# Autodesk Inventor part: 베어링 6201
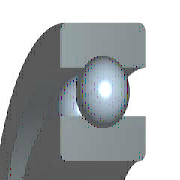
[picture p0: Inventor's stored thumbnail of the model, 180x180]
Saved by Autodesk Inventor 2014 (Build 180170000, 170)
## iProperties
Created: 2015-12
Part Number: 베어링 6201
Material: 강철, 연강
Description: 깊은 그루브 볼 베어링
Document SubType Name: Modeling
Standard: KS B 2023
Designer: mdu
Standards Organization: KS
Language: ko-KR
Size Designation: 6201 - 12 x 32 x 10
Categories: <MemberInstance><Categories><Category DisplayName="샤프트 부품" InternalName="7f7aeb1f-a693-4053-b835-cee3144e0d98" Mnemonic="SHFT"><Category DisplayName="베어링" Inter
Density: 7.86 g/cm^3
Mass: 32.7519 g
Surface Area: 42.5728 cm^2
Volume: 4.16691 cm^3
Appearance: 강철
Company: 한국ATC센터
IsCustomPart: 1
Author: mdu
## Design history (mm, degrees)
sketch "스케치" dims "d0" = 5.2 (= -0.26 x WD + 0.26 x BD)
  geometry: L1 (2.4, 11)-(7.6, 11); L2 (5, 11)-(5, 8.4); L3 (5, 11)-(5, 13.6); L4 (3.068, 9.26)-(0, 9.26); L5 (0, 6)-(10, 6); L6 (3.068, 12.74)-(0, 12.74); L7 (0, 16)-(10, 16); L8 (10, 6)-(10, 9.26); L9 (6.932, 9.26)-(10, 9.26); L10 (6.932, 12.74)-(10, 12.74); L11 (10, 16)-(10, 12.74); L12 (-1.4, 0)-(8.4, 0) reference; L13 (0, -0.3)-(0, 5.3) reference
  constraints: 22 end point, 4 point on line, 2 collinear, 2 perpendicular, 2 symmetric about line, 1 midpoint, 1 parallel, 14 other
  dimensions: "d9" = 12 diameter of L5 L12 (= WD); "d11" = 32 diameter of L7 L12 (= BD); "d12" = 10 distance between parallel lines of L8 L13 (= KB); "d13" = 18.52 diameter of L9 L12 (= 0.326 x BD + 0.674 x WD)
revolve "본체" stored, may be unused: angle "d6" = 90 deg
revolve "볼" stored, may be unused: angle "d7" = 90 deg
pattern_circular "IDS_ARRAYBALL[SIMPL:T]" dims angle "d3" = 360 deg
body "Solid1"
fillet "모깎기1" dims "d1" = 0.6 (= KRS)
other parameters: "WD" = 12 [user parameter; used in 5 equation terms], "BD" = 32 [user parameter; used in 5 equation terms], "KB" = 10 [user parameter; used in 1 equation term], "KRS" = 0.6 [user parameter; used in 1 equation term], "d4" = 0, "d5" = 0, "d8" = 0, "d14" = 0, "d15" = 0, "BBA" = 0 [user parameter], "BC0" = 3100000 [user parameter], "BC" = 6890000 [user parameter], "BR" = 16 (= 0.5 x BD) [user parameter], "WR" = 6 (= 0.5 x WD) [user parameter]
